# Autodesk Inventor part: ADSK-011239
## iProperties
Shininess: 0.0
Length Units: 11272
Angle Units: 11279
Time Units: 11290
Mass Units: 11286
Length Display Precision: 3
Angle Display Precision: 2
Compacted: True
Created: 1999-08
Part Number: ADSK-011239
Document SubType Name: Modeling
Density: 0.0
Volumn: 0.0
Area: 0.0
PropertySet Name: Model Information
Control State: 0
Master: False
Checked Out: False
Revision Number: -
Title: ADSK-011239
